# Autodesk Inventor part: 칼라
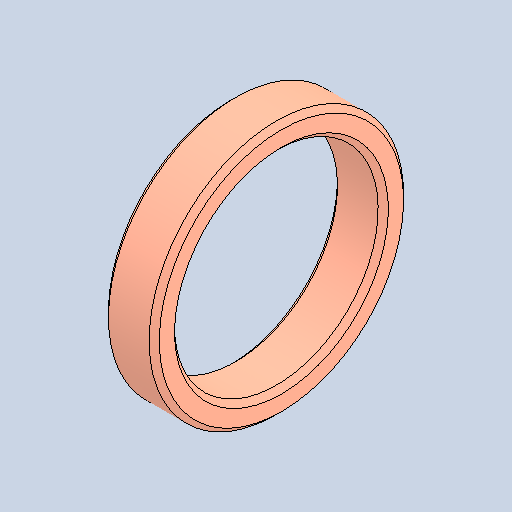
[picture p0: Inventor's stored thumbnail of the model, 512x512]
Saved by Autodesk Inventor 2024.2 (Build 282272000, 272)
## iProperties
Created: 2025-09
Part Number: 칼라
Material: 강철, 연강
Document SubType Name: Modeling
Designer: home
Density: 7.85 g/cm^3
Appearance: 기본값
Author: jhkim
Sending System: Autodesk Inventor 2026
Preprocessor: ST-DEVELOPER v20.1
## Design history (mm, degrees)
feature "솔리드1"
node "솔리드2"
